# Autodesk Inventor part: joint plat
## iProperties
Created: 2002-03
Part Number: joint plat
Material: Par défaut
Document SubType Name: Modélisation
Designer: BAVERGE
Control State: 0
Master: False
Checked Out: False
Shininess: 20.0
Length Units: 11269
Angle Units: 11279
Time Units: 11290
Mass Units: 11283
Length Display Precision: 3
Angle Display Precision: 2
Density: 0.0
Volumn: 0.0
Area: 0.0
PropertySet Name: Model Information
Author: BAVERGE
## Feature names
1. Extrusion1
